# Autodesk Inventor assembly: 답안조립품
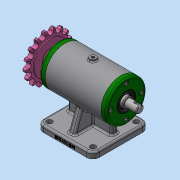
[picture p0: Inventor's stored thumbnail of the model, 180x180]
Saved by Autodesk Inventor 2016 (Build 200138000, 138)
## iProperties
Created: 2019-06
Part Number: 답안조립품
Material: 일반
Document SubType Name: Assembly
Designer: Administrator
Author: Administrator
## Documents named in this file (11)
- C:\Users\Administrator\Desktop\490604V1027\답안조립품.iam
- C:\Users\Administrator\Desktop\490604V1027\본체.ipt
- C:\Users\Administrator\Desktop\490604V1027\축.ipt
- C:\Users\Administrator\Desktop\490604V1027\베어링 6203.ipt
- C:\Users\Administrator\Desktop\490604V1027\스프로킷.ipt
- C:\Users\Administrator\Desktop\490604V1027\커버.ipt
- C:\Users\Administrator\Desktop\490604V1027\오일 실 17 30 5.ipt
- C:\Users\Administrator\Desktop\490604V1027\키 4x4x12.ipt
- C:\Users\Administrator\Desktop\490604V1027\스프링와셔.ipt
- C:\Users\Administrator\Desktop\490604V1027\평와셔.ipt
- C:\Users\Administrator\Desktop\490604V1027\볼트 M4.ipt
